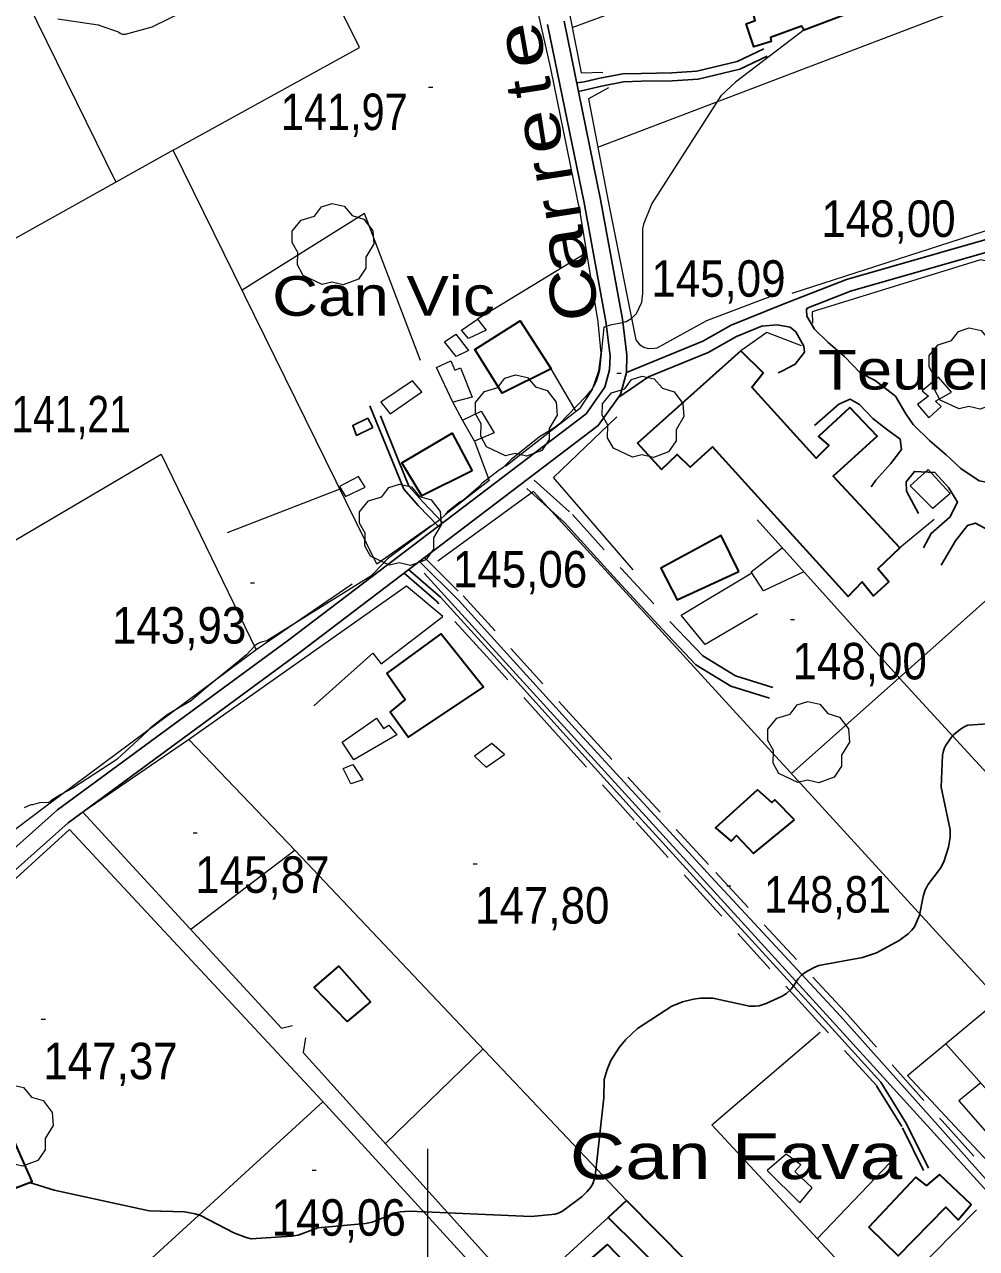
# Model space of a CAD drawing. Extents: x 480269 to 484877, y 4383588 to 4386804.
# Drawn here: x 481403.4 to 481631.7, y 4385501.1 to 4385794.6 of the extents above; entities that cross this region are included whole.
import ezdxf
from ezdxf.enums import TextEntityAlignment as Align

# ---------------------------------------------------------------- set-up
doc = ezdxf.new("R2010")
doc.units = 0
doc.header["$LTSCALE"] = 3.8
doc.linetypes.add('MEDIUM_DASHED', pattern=[4.5, 3, -1.5])
for name, color, linetype, lineweight in [('1', 7, 'Continuous', 13), ('21', 7, 'Continuous', 25), ('29', 7, 'Continuous', 13), ('36', 7, 'Continuous', 25), ('38', 7, 'Continuous', 25), ('47', 7, 'Continuous', 35), ('51', 7, 'Continuous', 13), ('7', 7, 'Continuous', 13), ('8', 7, 'Continuous', 25), ('9', 7, 'Continuous', 13)]:
    doc.layers.add(name, color=color, linetype=linetype, lineweight=lineweight)
doc.layers.add('5', color=7, linetype='Continuous')

msp = doc.modelspace()

# ---------------------------------------------------------------- linework, layer by layer
at = {"layer": '1'}
msp.add_line((481500, 4385525), (481500, 4385475), dxfattribs=at)
at = {"layer": '21'}
msp.add_lwpolyline([(481486.91, 4385698.03), (481485.68, 4385700.2), (481482.08, 4385698.49), (481482.98, 4385696.11)], close=True, dxfattribs=at)
at = {"layer": '29'}
for points in [[(481474.75, 4385732.3), (481470.21, 4385734.42), (481468.8, 4385736.96), (481468.9, 4385739.94), (481467.53, 4385742.35), (481467.57, 4385745.1), (481469.73, 4385747.7), (481472.92, 4385748.7), (481474.57, 4385750.89), (481477.14, 4385751.72), (481480, 4385751.07), (481481.95, 4385748.8), (481484.76, 4385747.98), (481486.89, 4385745.13), (481487.13, 4385742), (481485.25, 4385738.85), (481485.25, 4385736.17), (481483.43, 4385733.56), (481479.81, 4385732.22), (481477.04, 4385732.85)], [(481627.49, 4385702.45), (481622.95, 4385704.57), (481621.54, 4385707.11), (481621.64, 4385710.09), (481620.27, 4385712.5), (481620.31, 4385715.25), (481622.47, 4385717.85), (481625.66, 4385718.85), (481627.31, 4385721.04), (481629.88, 4385721.87), (481632.74, 4385721.22), (481634.69, 4385718.95), (481637.5, 4385718.13), (481639.63, 4385715.28), (481639.87, 4385712.15), (481637.99, 4385709), (481637.99, 4385706.32), (481636.17, 4385703.71), (481632.55, 4385702.37), (481629.78, 4385703)], [(481518.71, 4385691.22), (481514.17, 4385693.34), (481512.76, 4385695.88), (481512.86, 4385698.86), (481511.49, 4385701.27), (481511.53, 4385704.02), (481513.69, 4385706.62), (481516.88, 4385707.62), (481518.53, 4385709.81), (481521.1, 4385710.64), (481523.96, 4385709.99), (481525.91, 4385707.72), (481528.72, 4385706.9), (481530.85, 4385704.05), (481531.09, 4385700.92), (481529.21, 4385697.77), (481529.21, 4385695.09), (481527.39, 4385692.48), (481523.77, 4385691.14), (481521, 4385691.77)], [(481549.12, 4385690.89), (481544.58, 4385693.01), (481543.17, 4385695.55), (481543.27, 4385698.53), (481541.9, 4385700.94), (481541.94, 4385703.69), (481544.1, 4385706.29), (481547.29, 4385707.29), (481548.94, 4385709.48), (481551.51, 4385710.31), (481554.37, 4385709.66), (481556.32, 4385707.39), (481559.13, 4385706.57), (481561.26, 4385703.72), (481561.5, 4385700.59), (481559.62, 4385697.44), (481559.62, 4385694.76), (481557.8, 4385692.15), (481554.18, 4385690.81), (481551.41, 4385691.44)], [(481490.9, 4385664.98), (481486.36, 4385667.1), (481484.95, 4385669.64), (481485.05, 4385672.62), (481483.68, 4385675.03), (481483.72, 4385677.78), (481485.88, 4385680.38), (481489.07, 4385681.38), (481490.72, 4385683.57), (481493.29, 4385684.4), (481496.15, 4385683.75), (481498.1, 4385681.48), (481500.91, 4385680.66), (481503.04, 4385677.81), (481503.28, 4385674.68), (481501.4, 4385671.53), (481501.4, 4385668.85), (481499.58, 4385666.24), (481495.96, 4385664.9), (481493.19, 4385665.53)], [(481588.8, 4385612.88), (481584.26, 4385615), (481582.85, 4385617.54), (481582.95, 4385620.52), (481581.58, 4385622.93), (481581.62, 4385625.68), (481583.78, 4385628.28), (481586.97, 4385629.28), (481588.62, 4385631.47), (481591.19, 4385632.3), (481594.05, 4385631.65), (481596, 4385629.38), (481598.81, 4385628.56), (481600.94, 4385625.71), (481601.18, 4385622.58), (481599.3, 4385619.43), (481599.3, 4385616.75), (481597.48, 4385614.14), (481593.86, 4385612.8), (481591.09, 4385613.43)], [(481397.85, 4385520.95), (481393.31, 4385523.07), (481391.9, 4385525.61), (481392, 4385528.59), (481390.63, 4385531), (481390.67, 4385533.75), (481392.83, 4385536.35), (481396.02, 4385537.35), (481397.67, 4385539.54), (481400.24, 4385540.37), (481403.1, 4385539.72), (481405.05, 4385537.45), (481407.86, 4385536.63), (481409.99, 4385533.78), (481410.23, 4385530.65), (481408.35, 4385527.5), (481408.35, 4385524.82), (481406.53, 4385522.21), (481402.91, 4385520.87), (481400.14, 4385521.5)]]:
    msp.add_lwpolyline(points, close=True, dxfattribs=at)
at = {"layer": '36'}
for points in [[(481532.74, 4385795.43), (481541.49, 4385752.66), (481546.75, 4385724), (481547.82, 4385715.36), (481547.68, 4385711.2), (481546.25, 4385705.89), (481540.95, 4385698.46), (481469.12, 4385643.89), (481413.83, 4385603.2), (481387.79, 4385580.04), (481378.21, 4385569.43), (481368.09, 4385557.76), (481360.55, 4385549.93), (481356.99, 4385547.39), (481353.06, 4385545.63), (481341.54, 4385542.48), (481233.43, 4385521.3), (481226.84, 4385520.47), (481221.75, 4385519.81), (481211.59, 4385518.94), (481197.06, 4385519.31), (481189.31, 4385519.87), (481157.81, 4385525.71)], [(481528.8, 4385794.63), (481537.55, 4385751.89), (481542.78, 4385723.39), (481543.79, 4385715.19), (481543.68, 4385711.79), (481542.56, 4385707.64), (481538.04, 4385701.29), (481466.72, 4385647.1), (481411.3, 4385606.32), (481384.96, 4385582.9), (481375.2, 4385572.09), (481365.12, 4385560.48), (481358.05, 4385553.13), (481355.22, 4385550.94), (481351.5, 4385549.38), (481340.63, 4385546.4), (481232.83, 4385525.27), (481227.75, 4385524.48), (481218.5, 4385523.39), (481211.46, 4385522.97), (481205.65, 4385523.06), (481197.15, 4385523.39), (481189.77, 4385523.87), (481158.52, 4385529.67)]]:
    msp.add_lwpolyline(points, dxfattribs=at)
at = {"layer": '38'}
for points in [[(481760.24, 4385798.16), (481753.7, 4385791.52), (481746.77, 4385786.38), (481736.7, 4385780.94), (481716.23, 4385771.32), (481698.91, 4385764.33), (481667.07, 4385753.84), (481633.65, 4385743), (481600.45, 4385733.48), (481585.31, 4385727.58), (481572.78, 4385722.51), (481566.04, 4385718.67), (481547.68, 4385711.16)], [(481581.43, 4385787.03), (481574.92, 4385783.94), (481564.88, 4385781.55), (481558.63, 4385781.14), (481551.26, 4385781), (481547.01, 4385780.86), (481541.76, 4385779.86), (481536.19, 4385778.56)], [(481634.09, 4385740.02), (481601.4, 4385730.65), (481591.06, 4385726.63)], [(481645.62, 4385668.1), (481636.92, 4385677.56), (481637.63, 4385679.23), (481641.53, 4385682.25), (481640.38, 4385684.84), (481634.95, 4385684.73), (481632.26, 4385685.17), (481627.89, 4385688.13), (481624.4, 4385691.43), (481620.48, 4385694.8), (481616.44, 4385698.72), (481614.68, 4385701.28), (481612.25, 4385705.5), (481607.31, 4385709.27), (481603.73, 4385711.12), (481600, 4385715.03), (481596.04, 4385718.41), (481592.81, 4385721.6), (481590.93, 4385724.66), (481590.87, 4385726.2), (481591.06, 4385726.63)], [(481580.3, 4385722.34), (481574.08, 4385719.82), (481567.34, 4385715.99), (481552.98, 4385710.12), (481545.67, 4385705.07)], [(481580.1, 4385722.32), (481583.82, 4385722.64), (481586.97, 4385722.06), (481588.31, 4385720.91), (481590.28, 4385717.49), (481590.38, 4385716.07), (481588.2, 4385713.17), (481584.95, 4385711.5), (481584.06, 4385711.07)], [(481592.81, 4385698.51), (481598.6, 4385703.61), (481601.39, 4385704.81), (481603.56, 4385703.53), (481606.77, 4385700.12), (481610.04, 4385697.62), (481613.32, 4385695.23), (481613.66, 4385692.73), (481611.14, 4385689.36), (481607.5, 4385685.39), (481606.38, 4385683.77)], [(481502.52, 4385674.3), (481497.87, 4385679.21), (481494.34, 4385683.18), (481491.7, 4385689.7), (481486.2, 4385703.2)], [(481617.74, 4385677.34), (481614.87, 4385682.75), (481614.8, 4385684.93), (481616.75, 4385687.46), (481621.68, 4385687.24), (481624.99, 4385683.52), (481627.1, 4385680.11), (481625.26, 4385676.46), (481620.79, 4385672.59), (481618.91, 4385669.17)], [(481523.8, 4385683.38), (481532.87, 4385675.24), (481544.56, 4385662.28), (481556.25, 4385649.6), (481564.35, 4385641.12), (481572.75, 4385635.97), (481582, 4385633.09)], [(481623.19, 4385665.01), (481626.59, 4385670.78), (481629.45, 4385674.49), (481631.38, 4385675.08), (481635.7, 4385672.74), (481641.29, 4385667.74), (481642.94, 4385666.05)], [(481620.13, 4385520.39), (481614.89, 4385531.06), (481608.73, 4385541), (481594.6, 4385556.5), (481570.24, 4385583.18), (481550.59, 4385604.78), (481531.73, 4385625.65), (481515.26, 4385643.96), (481503.09, 4385657.27), (481495.47, 4385663.91)], [(481498.09, 4385665.9), (481507.46, 4385656.61), (481535.39, 4385625.76), (481568.02, 4385590.29), (481598.94, 4385556.93), (481622.28, 4385530.75), (481645.27, 4385505), (481666.95, 4385481.63), (481678.43, 4385469.2)]]:
    msp.add_lwpolyline(points, dxfattribs=at)
at = {"layer": '38', "linetype": 'MEDIUM_DASHED'}
for points in [[(481580.61, 4385788.76), (481574.28, 4385785.76), (481564.59, 4385783.45), (481558.55, 4385783.05), (481551.21, 4385782.91), (481546.8, 4385782.77), (481541.36, 4385781.73), (481537.53, 4385780.84), (481535.77, 4385780.63)], [(481503.64, 4385675.15), (481498.9, 4385680.15), (481495.54, 4385683.92), (481492.99, 4385690.23), (481487.49, 4385703.73)], [(481525.59, 4385685.37), (481534.76, 4385677.14), (481546.54, 4385664.08), (481558.2, 4385651.43), (481566.05, 4385643.22), (481573.86, 4385638.42), (481582.8, 4385635.65)], [(481499.28, 4385666.8), (481508.54, 4385657.65), (481536.49, 4385626.76), (481569.12, 4385591.3), (481600.04, 4385557.93), (481623.39, 4385531.74), (481646.37, 4385506), (481649.57, 4385502.55)], [(481618.93, 4385519.8), (481613.71, 4385530.41), (481607.65, 4385540.19), (481593.61, 4385555.59), (481569.25, 4385582.27), (481549.59, 4385603.87), (481530.73, 4385624.75), (481514.26, 4385643.05), (481502.15, 4385656.31), (481494.39, 4385663.08)]]:
    msp.add_lwpolyline(points, dxfattribs=at)
at = {"layer": '47'}
for points in [[(481601.12, 4385797.36), (481590.35, 4385793.29), (481589.7, 4385794.24), (481582.24, 4385791.52), (481582.39, 4385790.58), (481578.22, 4385789.29), (481576.43, 4385794.78), (481578.6, 4385795.55), (481577.5, 4385799.56), (481584.49, 4385801.99), (481584.74, 4385801.45), (481592.5, 4385804.16), (481593.87, 4385800.57), (481598.97, 4385802.52)], [(481529.68, 4385712.03), (481517.88, 4385706.26), (481511.34, 4385716.69), (481522.24, 4385723.59)], [(481600.9, 4385657.44), (481604.22, 4385661), (481606.96, 4385657.62), (481610.59, 4385661.02), (481607.95, 4385664.08), (481613.28, 4385669.1), (481597.28, 4385686.34), (481607.83, 4385695.93), (481601.24, 4385702.78), (481593.74, 4385695.81), (481596.26, 4385693.68), (481593.23, 4385690.67), (481577.8, 4385707.63), (481580.51, 4385711.07), (481575.17, 4385716.38), (481550.38, 4385694.27), (481556.07, 4385687.92), (481559.87, 4385691.54), (481562.97, 4385688.47), (481568.31, 4385693.37)], [(481510.68, 4385687.58), (481498.6, 4385681.59), (481493.84, 4385689.53), (481505.91, 4385696.63)], [(481574.66, 4385663.49), (481570.43, 4385672.11), (481555.93, 4385664.28), (481559.9, 4385656.63)], [(481513.39, 4385635.77), (481495.39, 4385623.78), (481491.02, 4385629.72), (481494.62, 4385632.7), (481490.22, 4385638.97), (481503.31, 4385648.49)], [(481587.97, 4385603.93), (481583.26, 4385608.71), (481582.56, 4385608.11), (481579.13, 4385611.08), (481569.09, 4385602), (481572.85, 4385598.81), (481574.08, 4385600.13), (481578.21, 4385595.86)], [(481486.33, 4385560.26), (481480.75, 4385555.56), (481472.84, 4385563.68), (481478.7, 4385568.81)], [(481399.25, 4385519.52), (481401.3, 4385515.67), (481405.21, 4385517.17), (481399.49, 4385530.08), (481380.23, 4385522.82), (481381.66, 4385519.01), (481385.15, 4385520.22), (481387.43, 4385515.02)], [(481622.76, 4385518.86), (481619.68, 4385516.28), (481617.08, 4385518.2), (481605.82, 4385506.28), (481612.83, 4385499.37), (481624.31, 4385511.02), (481627.28, 4385508.03), (481630.38, 4385511.7)], [(481557.75, 4385494.25), (481562.42, 4385497.81), (481547.74, 4385512.67), (481543.31, 4385508.58)], [(481530.27, 4385481.98), (481526.01, 4385487.14), (481543.14, 4385502.12), (481549.59, 4385495.44)]]:
    msp.add_lwpolyline(points, close=True, dxfattribs=at)
at = {"layer": '47', "lineweight": 13}
for points in [[(481512, 4385723.96), (481514.09, 4385721.29), (481509.86, 4385719.36), (481508.17, 4385721.31)], [(481504.06, 4385718.55), (481506.78, 4385720.4), (481509.84, 4385716.46), (481506.89, 4385714.99)], [(481510.69, 4385705.25), (481506.07, 4385704.05), (481502.17, 4385712.38), (481505.6, 4385713.94), (481506.52, 4385711.73), (481507.9, 4385712.33)], [(481498.62, 4385706.52), (481496.4, 4385709.15), (481488.84, 4385704.05), (481491.02, 4385701.24)], [(481625.64, 4385706.5), (481622.55, 4385710.03), (481618.64, 4385706.78), (481620.13, 4385705.5), (481617.49, 4385703.52), (481620.25, 4385700.29), (481623.21, 4385703), (481621.83, 4385704.3)], [(481515.98, 4385696.75), (481511.3, 4385694.71), (481508.37, 4385699.74), (481512.86, 4385701.87)], [(481625.37, 4385682.2), (481621.18, 4385678.57), (481615.73, 4385684.01), (481620.05, 4385687.89)], [(481485.06, 4385683.68), (481483.45, 4385686.22), (481478.9, 4385683.82), (481480.37, 4385681.48)], [(481482.32, 4385618.33), (481479.52, 4385622.54), (481487.74, 4385628.27), (481489.41, 4385625.8), (481490.7, 4385626.61), (481492.65, 4385624.3)], [(481518.45, 4385619.59), (481515.42, 4385622.21), (481511.3, 4385619.21), (481514.09, 4385616.53)], [(481484.48, 4385613.52), (481481.6, 4385612.56), (481479.75, 4385616.22), (481482.08, 4385617.15)], [(481589.31, 4385512.07), (481592.24, 4385515.72), (481588.07, 4385519.63), (481589.54, 4385521.21), (481586.03, 4385523.79), (481581.46, 4385519.81)]]:
    msp.add_lwpolyline(points, close=True, dxfattribs=at)
at = {"layer": '51'}
for p, q in [((481534.69, 4385793.88), (481643.35, 4385834.19)), ((481587.46, 4385730.22), (481652.73, 4385751.27)), ((481538.1, 4385739.91), (481512, 4385723.96)), ((481535.61, 4385701.82), (481529.68, 4385712.03)), ((481508.37, 4385699.74), (481506.07, 4385704.05)), ((481478.98, 4385683.2), (481451.99, 4385672.72)), ((481621.46, 4385675.9), (481613.28, 4385669.1)), ((481613.14, 4385637.96), (481643.38, 4385665.02)), ((481613.14, 4385637.96), (481587.3, 4385615.02)), ((481468.24, 4385596.63), (481443.24, 4385577.62)), ((481513.35, 4385548.99), (481489.9, 4385526.29)), ((481405.08, 4385472.53), (481474.92, 4385536.34)), ((481612.62, 4385523.51), (481593.46, 4385503.47)), ((481631.61, 4385510.38), (481608.61, 4385487.13))]:
    msp.add_line(p, q, dxfattribs=at)
for points in [[(481439.05, 4385764.51), (481483.67, 4385789.13), (481459.98, 4385836.93), (481514.58, 4385862.84), (481519.11, 4385831.83), (481522.84, 4385813.55), (481529.47, 4385784.09), (481536.49, 4385749.62), (481540.84, 4385723.34), (481541.54, 4385715.83), (481541.03, 4385711.5), (481539.51, 4385707.13), (481536.48, 4385702.5), (481518.7, 4385688.66)], [(481628.35, 4385860.83), (481528.78, 4385823.98), (481536.81, 4385783.04), (481542.03, 4385783.18)], [(481459.98, 4385836.93), (481401.64, 4385805.02), (481425.26, 4385756.81)], [(481540.85, 4385765.17), (481659.44, 4385810.46), (481647.67, 4385835.92)], [(481543.39, 4385779.42), (481538.63, 4385776.81), (481543.46, 4385751.47), (481549.93, 4385719.05), (481550.81, 4385717.89), (481551.87, 4385717.22), (481552.93, 4385716.92), (481554.45, 4385717), (481555.1, 4385717.08), (481567.01, 4385723.67), (481583.24, 4385729.82)], [(481500.9, 4385674.38), (481487.81, 4385665.19), (481439.05, 4385764.51), (481334.13, 4385705.9)], [(481498.29, 4385714.08), (481484.93, 4385749.29), (481455.57, 4385730.89)], [(481682.83, 4385569.62), (481685.86, 4385569.76), (481739.52, 4385616.65), (481740.23, 4385619.04), (481740, 4385622.39), (481634.85, 4385737.74), (481632.64, 4385738.19), (481592.21, 4385725.73), (481592.29, 4385723.01)], [(481589.65, 4385717.58), (481581.4, 4385720.78), (481575.17, 4385716.38)], [(481549.34, 4385663.89), (481530.18, 4385686.02), (481545.42, 4385700.52)], [(481511.3, 4385694.71), (481514.78, 4385685.26), (481504.31, 4385677.1)], [(481481.97, 4385660.41), (481459.14, 4385644.84), (481408.54, 4385607.22), (481383.27, 4385588.2), (481356.48, 4385644.69), (481436.14, 4385691.59), (481458.94, 4385644.7)], [(481690.22, 4385503.28), (481622.89, 4385576.1), (481525.44, 4385682.64), (481502.51, 4385665.98)], [(481679.54, 4385565.75), (481613.3, 4385637.77), (481579.05, 4385675.82)], [(481590.24, 4385663.39), (481580.53, 4385658.83), (481577.59, 4385663.4), (481585.04, 4385669.17)], [(481499.22, 4385663.05), (481597.3, 4385555.43), (481657.55, 4385489.12), (481765.67, 4385373.25), (481745.31, 4385335.89)], [(481579.17, 4385653.3), (481566.62, 4385645.95), (481560.86, 4385652.99), (481577.79, 4385663.11)], [(481472.78, 4385631.26), (481486.86, 4385643.88), (481488.9, 4385641.31), (481503.67, 4385652.64), (481495, 4385659.97), (481442.72, 4385623.14), (481417.36, 4385605.74), (481464.97, 4385554), (481467.64, 4385554.62)], [(481547.74, 4385512.67), (481468.27, 4385596.59), (481442.78, 4385623.19)], [(481571.15, 4385430.52), (481521.63, 4385485.21), (481474.7, 4385536.56), (481414.19, 4385601.57), (481394.98, 4385584.15), (481379.56, 4385569.01), (481368.93, 4385553.46), (481359.87, 4385539.34)], [(481652.41, 4385504.77), (481649.04, 4385506.26), (481615.13, 4385542.58), (481637, 4385560.85)], [(481619.86, 4385474.98), (481568.15, 4385530.78), (481594.18, 4385552.98)], [(481470.74, 4385551.64), (481470.21, 4385548.12), (481521.71, 4385490.99), (481523.96, 4385490.93), (481543.31, 4385508.58)], [(481658.54, 4385537.55), (481645.5, 4385526.51), (481624.28, 4385550.22)], [(481632.68, 4385540.84), (481627.37, 4385536.54), (481637.02, 4385525.57), (481642.04, 4385530.38)]]:
    msp.add_lwpolyline(points, dxfattribs=at)
at = {"layer": '7'}
for p, q in [((481500.24, 4385779.62), (481501.24, 4385779.62)), ((481545.43, 4385711.05), (481546.43, 4385711.05)), ((481497.83, 4385665.98), (481498.83, 4385665.98)), ((481457.55, 4385660.74), (481458.55, 4385660.74)), ((481587.03, 4385651.96), (481588.03, 4385651.96)), ((481443.79, 4385600.78), (481444.79, 4385600.78)), ((481510.91, 4385593.4), (481511.91, 4385593.4)), ((481571.77, 4385588.06), (481572.77, 4385588.06)), ((481407.38, 4385556.1), (481408.38, 4385556.1)), ((481472.31, 4385519.9), (481473.31, 4385519.9))]:
    msp.add_line(p, q, dxfattribs=at)
at = {"layer": '8'}
for points in [[(481616.17, 4385577.49), (481616.75, 4385578.28), (481617.05, 4385578.81), (481617.95, 4385581.07), (481618.87, 4385585.55), (481619.37, 4385587.1), (481619.5, 4385587.39), (481620.01, 4385588.31), (481622.98, 4385592.29), (481623.79, 4385593.85), (481624.95, 4385597.37), (481625.31, 4385599.75), (481625.31, 4385601.51), (481623.15, 4385611.77), (481623.53, 4385619.41), (481623.72, 4385620.48), (481623.98, 4385621.22), (481624.18, 4385621.65), (481625.4, 4385623.46), (481626.13, 4385624.28), (481627.77, 4385625.65), (481628.86, 4385626.31), (481629.57, 4385626.64), (481646.26, 4385627.73)], [(481404.56, 4385516.92), (481410.46, 4385515.1), (481433.28, 4385510.19), (481441.73, 4385509.92), (481444.3, 4385509.47), (481445.6, 4385509.06), (481453.59, 4385504.92), (481456.5, 4385503.81), (481457.69, 4385503.49), (481467.42, 4385504.06), (481469.02, 4385504.36), (481473.7, 4385506.1), (481485.15, 4385507.13), (481486.75, 4385507.44), (481492.43, 4385509.68), (481493.48, 4385509.94), (481495.67, 4385510.06), (481524.84, 4385508.81), (481530.63, 4385509.35), (481531.61, 4385509.68), (481532.39, 4385510.05), (481537.11, 4385513.62), (481538.23, 4385514.7), (481539.16, 4385515.85), (481539.67, 4385516.63), (481540.19, 4385518.49), (481542.26, 4385537.26), (481542.38, 4385541.64), (481543.07, 4385544.07), (481543.98, 4385546.19), (481545.92, 4385549.31), (481547.44, 4385551.2), (481550.38, 4385553.86), (481558.56, 4385559.25), (481561.15, 4385560.26), (481563.81, 4385560.94), (481565.49, 4385561.17), (481568.4, 4385561.14), (481577.21, 4385559.22), (481578.6, 4385559.21), (481579.49, 4385559.33), (481581.24, 4385559.86), (481585.02, 4385561.63), (481586.08, 4385562.31), (481587.06, 4385563.13), (481587.22, 4385563.31), (481587.66, 4385563.92), (481588.87, 4385565.77), (481589.6, 4385566.59), (481590.1, 4385567.02), (481591.18, 4385567.74), (481592.88, 4385568.61), (481593.83, 4385568.97), (481604.28, 4385570.88), (481607.66, 4385572.02), (481613.14, 4385574.98), (481615.29, 4385576.6), (481616.17, 4385577.49)]]:
    msp.add_lwpolyline(points, dxfattribs=at)
at = {"layer": '9'}
for points in [[(481411.37, 4385795.97), (481421, 4385794.57), (481421.1, 4385794.54), (481421.26, 4385794.47), (481421.41, 4385794.4), (481425.66, 4385792.94), (481425.96, 4385792.8), (481426.3, 4385792.55), (481426.63, 4385792.36), (481426.9, 4385792.3), (481427.55, 4385792.28), (481433.98, 4385794.1), (481434.31, 4385794.23), (481441.18, 4385797.54)], [(481590.3, 4385793.36), (481573.86, 4385780.8), (481570.34, 4385777.54), (481553.77, 4385751.7), (481551.8, 4385746.71), (481551.57, 4385745.64), (481551.57, 4385730.16), (481551.56, 4385730.12), (481551.31, 4385728.01), (481551.3, 4385727.99), (481551.28, 4385727.94), (481550.05, 4385725.27), (481548.85, 4385724.04), (481547.83, 4385723.38), (481547.69, 4385723.34), (481547.52, 4385723.31), (481546.32, 4385722.98), (481543.77, 4385722.56), (481542.42, 4385722.02), (481542.39, 4385722.02), (481542.28, 4385722.01), (481541.25, 4385711.64), (481540.49, 4385709.17), (481540.17, 4385708.51), (481539.13, 4385706.8), (481539.03, 4385706.69), (481538.96, 4385706.65), (481538.91, 4385706.61), (481537.85, 4385705.32), (481531.69, 4385698.89), (481530.31, 4385697.82), (481526.87, 4385695.79), (481519.97, 4385690.22), (481518.15, 4385688.4), (481516.89, 4385687.51), (481513.04, 4385684.53), (481512.23, 4385683.65), (481508.71, 4385680.68), (481507.84, 4385680.19), (481504.8, 4385677.73), (481504.47, 4385677.36), (481504.29, 4385677.12), (481502.97, 4385675.86), (481490.39, 4385666.5), (481489.74, 4385665.87), (481489.37, 4385665.36), (481486.74, 4385662.69), (481486.43, 4385662.32), (481461.48, 4385646.86)], [(481461.48, 4385646.86), (481460.14, 4385646.49), (481459.57, 4385646.3), (481459.24, 4385646.12), (481458.66, 4385645.68), (481456.56, 4385643.49), (481447.43, 4385635.98), (481443.06, 4385632.31), (481442.97, 4385632.27), (481441.08, 4385631.14), (481440.92, 4385631.09), (481437.56, 4385629.13), (481433.53, 4385625.88), (481432.64, 4385624.9), (481425.69, 4385618.51), (481425.54, 4385618.37), (481414.96, 4385611.51), (481412.09, 4385609.99), (481409.68, 4385608.46), (481409.38, 4385608.19), (481409.15, 4385608.11), (481409.03, 4385608.09), (481406.97, 4385607.96), (481405.31, 4385607.55), (481405, 4385607.53), (481404.69, 4385607.46), (481404.45, 4385607.37), (481403.26, 4385606.79)]]:
    msp.add_lwpolyline(points, dxfattribs=at)

# ---------------------------------------------------------------- texts
at = {"layer": '5'}
for s, rotation, width, p in [('e', 99.906, 1.35, (481527.55, 4385790.46)), ('t', 98.903, 1.1, (481529.52, 4385780.24)), ('e', 98.903, 1.3, (481531.8, 4385769.6)), ('r', 98.903, 1.15, (481534.31, 4385760.11)), ('r', 98.903, 1.15, (481536.59, 4385751.08)), ('a', 98.903, 1.35, (481537.73, 4385741.32)), ('C', 96.168, 1.2, (481540.33, 4385730.42))]:
    msp.add_text(s, height=10.99, rotation=rotation, dxfattribs=dict(at, width=width)).set_placement(p, align=Align.CENTER)
at = {"layer": '5', "width": 1.2}
for s, p in [('Can Vic', (481516.13, 4385724.78)), ('Teulera de Son Segu[', (481741.94, 4385707.1))]:
    msp.add_text(s, height=9.5, dxfattribs=at).set_placement(p, align=Align.RIGHT)
at = {"layer": '5', "width": 1.25}
msp.add_text('Can Fava', height=11, dxfattribs=at).set_placement((481534.13, 4385517.78))
at = {"layer": '7'}
for s, width, p in [('141,97', 0.85, (481464.83, 4385769.31)), ('148,00', 0.9, (481594.43, 4385743.68)), ('145,09', 0.9, (481553.66, 4385729.34)), ('141,21', 0.8, (481400.23, 4385696.81)), ('145,06', 0.9, (481506.09, 4385659.64)), ('143,93', 0.9, (481424.34, 4385646.19)), ('148,00', 0.9, (481587.53, 4385637.59)), ('145,87', 0.9, (481444.29, 4385586.41)), ('148,81', 0.85, (481580.7, 4385581.68)), ('147,80', 0.9, (481511.41, 4385579.03)), ('147,37', 0.9, (481407.88, 4385541.73)), ('149,06', 0.9, (481462.6, 4385504.2))]:
    msp.add_text(s, height=8.75, dxfattribs=dict(at, width=width)).set_placement(p)

doc.saveas('drawing.dxf')
